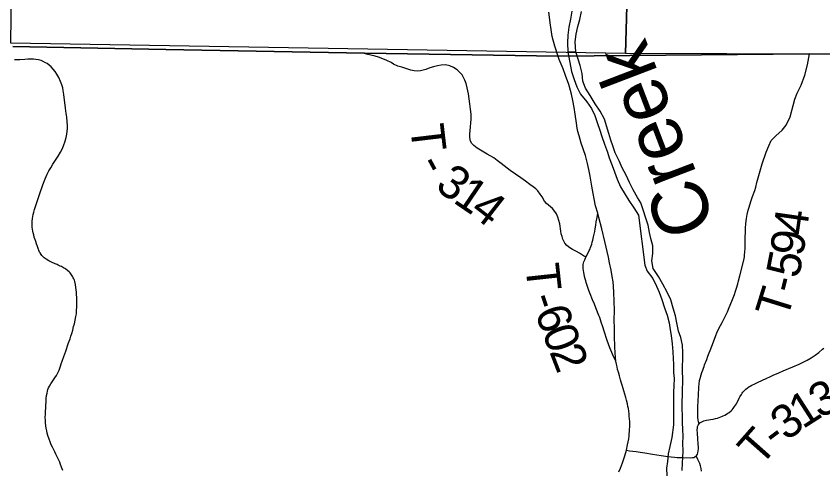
# Model space of a CAD drawing. Extents: x 0 to 34, y 0 to 22.
# Drawn here: x 4.406 to 5.767, y 16.7 to 17.465 of the extents above; entities that cross this region are included whole.
import ezdxf

# ---------------------------------------------------------------- set-up
doc = ezdxf.new("R2010")
doc.units = 0
for name, color, linetype in [('GM_X_Corporation', 7, 'Continuous'), ('GM_X_Major_River', 7, 'Continuous'), ('GM_X_Major_River_Text', 7, 'Continuous'), ('GM_X_State_Route', 7, 'Continuous'), ('GM_X_Township_Road', 7, 'Continuous'), ('GM_X_Township_Road_Text', 7, 'Continuous'), ('GM_X_Township_Text', 7, 'Continuous')]:
    doc.layers.add(name, color=color, linetype=linetype)

msp = doc.modelspace()

# ---------------------------------------------------------------- linework, layer by layer
at = {"layer": 'GM_X_Corporation'}
for points in [[(4.4097, 18.3961), (5.4623, 18.3997), (5.4343, 17.4017), (4.3969, 17.419)], [(6.4692, 18.391), (6.4651, 17.8343), (6.4606, 17.3985), (5.4343, 17.4017), (5.4623, 18.3997)]]:
    msp.add_lwpolyline(points, close=True, dxfattribs=at)
msp.add_lwpolyline([(8.9, 14.1), (8.9, 16.8499), (8.7964, 16.8516), (8.7214, 16.8529), (7.8171, 16.8691), (6.5825, 16.8858), (6.4571, 16.891), (6.4525, 17.3965), (6.1753, 17.3961), (5.7441, 17.4015), (5.3204, 17.3974), (4.9935, 17.4026), (4.6584, 17.4085), (4.4004, 17.4134)], dxfattribs=at)
at = {"layer": 'GM_X_Major_River'}
msp.add_line((5.3369, 17.4047), (5.3502, 17.4046), dxfattribs=at)
for points in [[(5.3438, 17.4732), (5.3411, 17.4598), (5.3383, 17.4461), (5.3367, 17.4328), (5.3362, 17.4199), (5.3369, 17.4047)], [(5.3502, 17.4046), (5.3494, 17.4213), (5.3507, 17.4342), (5.3534, 17.4472), (5.357, 17.4594), (5.3598, 17.4727)], [(5.3369, 17.4047), (5.3432, 17.3717), (5.3476, 17.3581), (5.3519, 17.3457), (5.3582, 17.3332), (5.3686, 17.3205), (5.3767, 17.3092), (5.3822, 17.2971), (5.3865, 17.2854), (5.3905, 17.2726), (5.394, 17.262), (5.3987, 17.2492), (5.4038, 17.2356), (5.4066, 17.2258), (5.4114, 17.213), (5.4153, 17.2024), (5.42, 17.19), (5.4255, 17.1771), (5.4336, 17.164), (5.4395, 17.1538), (5.4483, 17.1418), (5.4561, 17.129), (5.4669, 17.0447)], [(5.46, 17.15), (5.4542, 17.1593), (5.4468, 17.1717), (5.4409, 17.1845), (5.4351, 17.1966), (5.4285, 17.209), (5.4234, 17.2211), (5.4164, 17.2343), (5.4128, 17.246), (5.4093, 17.2558), (5.4061, 17.2667), (5.3989, 17.2909), (5.3912, 17.3045), (5.383, 17.3169), (5.3745, 17.3312), (5.3664, 17.3436), (5.362, 17.3553), (5.3607, 17.3682), (5.3575, 17.3814), (5.3502, 17.4046)], [(5.5297, 16.6987), (5.53, 16.7112), (5.531, 16.7215), (5.5313, 16.731), (5.5308, 16.7454), (5.5311, 16.7556), (5.5306, 16.7689), (5.5301, 16.7788), (5.5298, 16.8156), (5.5301, 16.8251), (5.5303, 16.8357), (5.5306, 16.8471), (5.5304, 16.8726), (5.531, 16.8881), (5.5309, 16.898), (5.5304, 16.9102), (5.5273, 16.923), (5.5237, 16.9336), (5.5206, 16.9476), (5.5182, 16.9594), (5.5146, 16.9726), (5.5107, 16.9867), (5.5045, 16.9995), (5.4968, 17.0131), (5.4899, 17.0259), (5.481, 17.0391), (5.4786, 17.052), (5.48, 17.0646), (5.4799, 17.0778), (5.4767, 17.09), (5.4744, 17.1002), (5.4724, 17.1123), (5.46, 17.15)], [(5.4669, 17.0447), (5.4708, 17.0349), (5.48, 17.0224), (5.4866, 17.0096), (5.4909, 16.9994), (5.4955, 16.9869), (5.4998, 16.9733), (5.5041, 16.9608), (5.508, 16.9479), (5.5093, 16.9358), (5.5109, 16.9263), (5.5126, 16.9123), (5.5138, 16.899), (5.5147, 16.8876), (5.5152, 16.8774), (5.5153, 16.8641), (5.5161, 16.8538), (5.5155, 16.8413), (5.5152, 16.831), (5.5149, 16.8212), (5.515, 16.8109), (5.5148, 16.7972), (5.515, 16.7756), (5.5121, 16.7543), (5.5089, 16.7391), (5.5063, 16.7269), (5.5049, 16.714), (5.5035, 16.7026), (5.5036, 16.6897)]]:
    msp.add_lwpolyline(points, dxfattribs=at)
at = {"layer": 'GM_X_State_Route'}
for points in [[(5.308, 17.4463), (5.3075, 17.4494), (5.3046, 17.4715)], [(5.3206, 17.3968), (5.3147, 17.4143), (5.3105, 17.4303), (5.308, 17.4463)], [(5.4228, 16.6966), (5.4254, 16.7027), (5.4288, 16.712), (5.4328, 16.7237), (5.4355, 16.7329), (5.4377, 16.7423), (5.4395, 16.752), (5.4401, 16.7565), (5.4405, 16.7605), (5.4409, 16.7645), (5.441, 16.7679), (5.4412, 16.7725), (5.4412, 16.7772), (5.4411, 16.7814), (5.4409, 16.7858), (5.4405, 16.7903), (5.4401, 16.7944), (5.4395, 16.799), (5.4389, 16.8031), (5.4382, 16.8068), (5.4372, 16.8114), (5.4359, 16.8171), (5.4347, 16.8216), (5.4331, 16.8276), (5.4315, 16.8331), (5.4303, 16.8371), (5.4287, 16.8424), (5.427, 16.8477), (5.4257, 16.8518), (5.4238, 16.8583), (5.4221, 16.8644), (5.4208, 16.8689), (5.4198, 16.8734), (5.4189, 16.8783), (5.418, 16.8831), (5.4172, 16.89), (5.4166, 16.8968), (5.416, 16.908), (5.4158, 16.9123), (5.4156, 16.9204), (5.4155, 16.9272), (5.4153, 16.9365), (5.4153, 16.9427), (5.4152, 16.9482), (5.4151, 16.9526), (5.4153, 16.9687), (5.4151, 16.9843), (5.4146, 16.9991), (5.4138, 17.0096), (5.413, 17.017), (5.4118, 17.0256), (5.4098, 17.0365), (5.4073, 17.0487), (5.4053, 17.0584), (5.3993, 17.0851), (5.3942, 17.1062), (5.389, 17.1254), (5.3872, 17.1324), (5.3837, 17.1452), (5.3811, 17.1567), (5.3793, 17.1659), (5.3773, 17.1782), (5.3746, 17.1953), (5.3724, 17.2063), (5.37, 17.2165), (5.3663, 17.2296), (5.3593, 17.2509), (5.3557, 17.2628), (5.3539, 17.2701), (5.3526, 17.2762), (5.3513, 17.2842), (5.3494, 17.2996), (5.3477, 17.3106), (5.3454, 17.3228), (5.3431, 17.333), (5.3414, 17.3396), (5.3382, 17.3495), (5.3328, 17.3647), (5.3287, 17.3757), (5.3223, 17.3919), (5.3206, 17.3968)]]:
    msp.add_lwpolyline(points, dxfattribs=at)
at = {"layer": 'GM_X_Township_Road'}
for points in [[(5.3673, 17.0584), (5.3653, 17.0595), (5.363, 17.0608), (5.3562, 17.0651), (5.3512, 17.068), (5.3446, 17.0715), (5.3404, 17.0744), (5.3352, 17.0784), (5.3315, 17.0822), (5.3281, 17.0889), (5.3272, 17.0931), (5.3258, 17.0977), (5.3252, 17.1023), (5.323, 17.1145), (5.3217, 17.12), (5.3199, 17.1259), (5.3177, 17.1313), (5.3146, 17.1353), (5.3108, 17.1404), (5.3007, 17.149), (5.2975, 17.1531), (5.2934, 17.1602), (5.2902, 17.1647), (5.2862, 17.1701), (5.2828, 17.1736), (5.2785, 17.1772), (5.2727, 17.1812), (5.2651, 17.1864), (5.2572, 17.1923), (5.2482, 17.1985), (5.2396, 17.2048), (5.2244, 17.2165), (5.2174, 17.2213), (5.2119, 17.2259), (5.2008, 17.2321), (5.1922, 17.237), (5.1836, 17.2423), (5.1783, 17.2469), (5.175, 17.25), (5.1727, 17.2543), (5.1716, 17.2604), (5.1713, 17.2661), (5.1722, 17.2718), (5.1739, 17.291), (5.1739, 17.2994), (5.1728, 17.3077), (5.1714, 17.3168), (5.1692, 17.334), (5.1672, 17.3442), (5.1652, 17.3511), (5.1629, 17.3569), (5.1606, 17.3616), (5.1583, 17.3658), (5.1553, 17.3694), (5.1501, 17.3741), (5.1436, 17.3784), (5.1375, 17.3812), (5.1302, 17.3828), (5.1231, 17.3823), (5.1168, 17.3812), (5.11, 17.3794), (5.1038, 17.3774), (5.0974, 17.3748), (5.0883, 17.3726), (5.0832, 17.3721), (5.0778, 17.3724), (5.072, 17.3735), (5.0649, 17.3758), (5.0567, 17.3787), (5.0502, 17.3807), (5.0429, 17.384), (5.0385, 17.3864), (5.0314, 17.39), (5.0247, 17.393), (5.0173, 17.3956), (5.0115, 17.3973), (5.0046, 17.3991), (4.9993, 17.4003), (4.9937, 17.402)], [(5.5581, 16.7772), (5.5572, 16.7809), (5.5565, 16.784), (5.556, 16.7884), (5.556, 16.7933), (5.556, 16.797), (5.5561, 16.8008), (5.5563, 16.8057), (5.5567, 16.8169), (5.557, 16.8256), (5.5577, 16.8393), (5.5582, 16.8448), (5.559, 16.8504), (5.5598, 16.8538), (5.5618, 16.8603), (5.563, 16.8638), (5.5643, 16.8681), (5.5654, 16.8711), (5.5665, 16.8742), (5.5676, 16.8768), (5.5686, 16.8795), (5.5697, 16.8822), (5.5713, 16.8862), (5.5732, 16.8914), (5.5754, 16.8971), (5.577, 16.9011), (5.5824, 16.9156), (5.5866, 16.9263), (5.5884, 16.9307), (5.5912, 16.9368), (5.5945, 16.9434), (5.5969, 16.9484), (5.6, 16.9539), (5.6035, 16.9609), (5.6061, 16.9663), (5.6091, 16.9736), (5.6133, 16.984), (5.6155, 16.9898), (5.6177, 16.9956), (5.6196, 17.0009), (5.6212, 17.006), (5.6235, 17.0133), (5.6247, 17.0187), (5.6271, 17.0271), (5.6337, 17.0536), (5.6347, 17.0591), (5.6351, 17.0621), (5.6356, 17.0677), (5.6359, 17.0732), (5.636, 17.0782), (5.6361, 17.0794), (5.6361, 17.0818), (5.6361, 17.0831), (5.6361, 17.0861), (5.6362, 17.0928), (5.6363, 17.1001), (5.6366, 17.1075), (5.6372, 17.115), (5.6381, 17.1236), (5.6393, 17.1304), (5.641, 17.1376), (5.6425, 17.143), (5.6436, 17.1466), (5.6462, 17.1541), (5.6485, 17.1609), (5.652, 17.1711), (5.6537, 17.1764), (5.6558, 17.1841), (5.6645, 17.2159), (5.6714, 17.2356), (5.6761, 17.2459), (5.68, 17.2549), (5.6877, 17.2631), (5.6983, 17.2728), (5.7052, 17.2809), (5.7121, 17.2953), (5.7168, 17.3141), (5.7196, 17.325), (5.7236, 17.3347), (5.7302, 17.3482), (5.7365, 17.3653), (5.7412, 17.3825), (5.7443, 17.401)], [(4.4848, 16.6987), (4.4828, 16.7043), (4.481, 16.7089), (4.4795, 16.7128), (4.4774, 16.7174), (4.4753, 16.7219), (4.4731, 16.7263), (4.4712, 16.7302), (4.4689, 16.7346), (4.4673, 16.7379), (4.4652, 16.7423), (4.4633, 16.7469), (4.4615, 16.7518), (4.4595, 16.7578), (4.4585, 16.7617), (4.4576, 16.7657), (4.4567, 16.77), (4.4562, 16.7741), (4.4557, 16.7791), (4.4554, 16.7832), (4.4552, 16.7885), (4.4553, 16.793), (4.4555, 16.7982), (4.4559, 16.8046), (4.4561, 16.8092), (4.4564, 16.8142), (4.4569, 16.8201), (4.4575, 16.8252), (4.4581, 16.8293), (4.4588, 16.8328), (4.4595, 16.8355), (4.4608, 16.8382), (4.4622, 16.8408), (4.4648, 16.8451), (4.4667, 16.8482), (4.4692, 16.8517), (4.4715, 16.8553), (4.4739, 16.859), (4.4764, 16.8634), (4.4786, 16.868), (4.4798, 16.8711), (4.4808, 16.8745), (4.4822, 16.8786), (4.4836, 16.883), (4.4867, 16.8911), (4.4899, 16.8999), (4.4911, 16.9034), (4.4929, 16.9087), (4.4946, 16.9139), (4.497, 16.921), (4.4983, 16.9252), (4.4997, 16.9299), (4.5015, 16.9355), (4.503, 16.9413), (4.5044, 16.9461), (4.5058, 16.9522), (4.5069, 16.9586), (4.5076, 16.963), (4.508, 16.9684), (4.5083, 16.9746), (4.5083, 16.9802), (4.5083, 16.9864), (4.5077, 16.9994), (4.507, 17.0075), (4.5062, 17.0123), (4.5049, 17.0172), (4.5042, 17.0195), (4.5032, 17.0218), (4.5025, 17.0234), (4.5017, 17.0252), (4.5006, 17.027), (4.4994, 17.0289), (4.497, 17.0318), (4.4953, 17.0336), (4.4935, 17.0353), (4.4919, 17.0366), (4.4901, 17.038), (4.4881, 17.0394), (4.486, 17.0407), (4.4827, 17.0425), (4.4805, 17.0435), (4.4772, 17.0451), (4.4755, 17.0459), (4.4721, 17.0473), (4.4709, 17.0477), (4.467, 17.0494), (4.461, 17.0525), (4.4567, 17.055), (4.4532, 17.0576), (4.4505, 17.0602), (4.4493, 17.0614), (4.4481, 17.063), (4.4464, 17.0656), (4.4457, 17.0669), (4.4449, 17.0684), (4.4432, 17.073), (4.442, 17.0765), (4.4403, 17.0812), (4.4391, 17.0847), (4.4376, 17.0894), (4.4367, 17.0923), (4.4357, 17.0959), (4.4347, 17.0994), (4.4341, 17.1024), (4.4337, 17.1057), (4.4333, 17.1093), (4.4332, 17.1122), (4.4331, 17.1151), (4.4331, 17.1187), (4.4337, 17.1236), (4.4343, 17.1273), (4.435, 17.1303), (4.4361, 17.1346), (4.4372, 17.1387), (4.4402, 17.1489), (4.4452, 17.1642), (4.4511, 17.1806), (4.4551, 17.1904), (4.4586, 17.1983), (4.4614, 17.2038), (4.4644, 17.2093), (4.4681, 17.215), (4.4772, 17.229), (4.481, 17.2354), (4.4841, 17.2415), (4.4866, 17.2478), (4.4882, 17.2525), (4.4904, 17.2603), (4.4916, 17.2657), (4.4923, 17.2707), (4.4926, 17.275), (4.4925, 17.2799), (4.492, 17.2874), (4.4913, 17.2947), (4.4909, 17.2978), (4.4906, 17.3008), (4.4894, 17.3094), (4.4881, 17.3192), (4.4872, 17.3278), (4.4866, 17.3328), (4.4856, 17.3394), (4.4847, 17.3437), (4.4831, 17.3491), (4.4809, 17.3549), (4.478, 17.3611), (4.4746, 17.367), (4.4716, 17.3717), (4.4685, 17.3756), (4.4651, 17.3793), (4.4619, 17.3822), (4.4584, 17.3847), (4.4557, 17.3863), (4.4518, 17.3882), (4.448, 17.3898), (4.4438, 17.391), (4.4395, 17.3917), (4.4351, 17.3922), (4.4307, 17.3922), (4.4258, 17.3922), (4.4208, 17.3919), (4.4122, 17.3914), (4.4035, 17.3909)], [(5.3673, 17.0584), (5.3677, 17.0592), (5.373, 17.0697), (5.3742, 17.0723), (5.3752, 17.0748), (5.3763, 17.0776), (5.377, 17.0801), (5.3781, 17.0837), (5.379, 17.0872), (5.3803, 17.0929), (5.3813, 17.0974), (5.3821, 17.1017), (5.3829, 17.106), (5.3839, 17.1125), (5.3847, 17.1178), (5.386, 17.1255), (5.3872, 17.1324)], [(5.418, 16.8831), (5.4123, 16.8949), (5.411, 16.8976), (5.4078, 16.9057), (5.4034, 16.9179), (5.3981, 16.9337), (5.3958, 16.9408), (5.3931, 16.949), (5.3905, 16.9566), (5.3892, 16.96), (5.3841, 16.973), (5.3816, 16.9793), (5.3786, 16.9866), (5.3744, 16.9969), (5.3723, 17.002), (5.371, 17.0055), (5.3697, 17.0091), (5.3687, 17.0125), (5.3678, 17.0159), (5.367, 17.0188), (5.3661, 17.0218), (5.3649, 17.0259), (5.3641, 17.0296), (5.3635, 17.0325), (5.3631, 17.0359), (5.3628, 17.0395), (5.3627, 17.0416), (5.3628, 17.0441), (5.3629, 17.0459), (5.3633, 17.0483), (5.3639, 17.0507), (5.3652, 17.0542), (5.3668, 17.0575), (5.3673, 17.0584)], [(5.5581, 16.7772), (5.5596, 16.779), (5.5616, 16.7805), (5.5637, 16.7816), (5.5661, 16.7824), (5.5709, 16.7834), (5.5745, 16.7841), (5.5775, 16.7845), (5.5819, 16.7854), (5.586, 16.7862), (5.5895, 16.7873), (5.5919, 16.7881), (5.5948, 16.7891), (5.5976, 16.7903), (5.5988, 16.7908), (5.6015, 16.7921), (5.6047, 16.794), (5.6068, 16.7953), (5.6088, 16.7968), (5.6121, 16.7995), (5.6139, 16.8013), (5.6159, 16.8036), (5.6182, 16.8066), (5.6199, 16.8091), (5.6211, 16.8112), (5.6224, 16.8136), (5.626, 16.8207), (5.6271, 16.8229), (5.6296, 16.8272), (5.631, 16.8293), (5.6321, 16.8307), (5.6346, 16.8335), (5.6373, 16.8361), (5.6392, 16.8377), (5.6423, 16.8397), (5.6444, 16.8409), (5.6471, 16.8424), (5.6522, 16.8448), (5.6578, 16.8475), (5.6712, 16.8538), (5.6785, 16.8572), (5.683, 16.8593), (5.6926, 16.8636), (5.7001, 16.8668), (5.7161, 16.8735), (5.7269, 16.8782), (5.7303, 16.8797), (5.7337, 16.8813), (5.737, 16.8829), (5.7403, 16.8846), (5.7473, 16.8887), (5.754, 16.8931), (5.7604, 16.898), (5.7666, 16.9032), (5.7685, 16.9048)], [(5.5531, 16.7233), (5.5545, 16.7249), (5.5553, 16.7265), (5.5562, 16.7288), (5.5568, 16.7319), (5.5571, 16.7352), (5.5571, 16.738), (5.5568, 16.743), (5.5562, 16.7523), (5.5553, 16.7616), (5.5551, 16.7672), (5.5553, 16.7702), (5.5558, 16.7727), (5.5567, 16.775), (5.5581, 16.7772)], [(5.4355, 16.7329), (5.4409, 16.7322), (5.4519, 16.7308), (5.4587, 16.7297), (5.4666, 16.7284), (5.4795, 16.7264), (5.4942, 16.7242), (5.5052, 16.7225), (5.5169, 16.7211), (5.5213, 16.7208), (5.5237, 16.7207), (5.5293, 16.7206), (5.5442, 16.7202), (5.5473, 16.7205), (5.5491, 16.7209), (5.5509, 16.7216), (5.5531, 16.7233)], [(5.5621, 16.6979), (5.5616, 16.7022), (5.5607, 16.7065), (5.5594, 16.7106), (5.5573, 16.7152), (5.5562, 16.7174), (5.5531, 16.7233)]]:
    msp.add_lwpolyline(points, dxfattribs=at)
at = {"layer": 'GM_X_Township_Text'}
msp.add_lwpolyline([(4.4004, 17.4134), (4.6584, 17.4085), (4.9935, 17.4026), (5.3204, 17.3974), (5.7441, 17.4015), (6.1753, 17.3961), (6.4525, 17.3965), (6.4571, 16.891), (6.5825, 16.8858), (7.8171, 16.8691), (8.7214, 16.8529), (8.7964, 16.8516), (8.9, 16.8499)], dxfattribs=at)

# ---------------------------------------------------------------- texts
at = {"layer": 'GM_X_Major_River_Text'}
msp.add_text('Creek', height=0.09469, rotation=110.9056, dxfattribs=at).set_placement((5.5875, 17.1135))
at = {"layer": 'GM_X_Township_Road_Text'}
for s, rotation, p in [('T', 276.7827, (5.0705, 17.2796)), ('-', 298.3597, (5.0825, 17.2153)), ('3', 323.0882, (5.1109, 17.1746)), ('1', 325.7708, (5.1413, 17.1519)), ('4', 322.031, (5.1694, 17.1328)), ('4', 81.8922, (5.7388, 17.0934)), ('9', 81.2838, (5.7334, 17.0582)), ('5', 79.0728, (5.7264, 17.0214)), ('T', 276.1921, (5.265, 17.045)), ('-', 75.7988, (5.7199, 16.9954)), ('T', 72.7117, (5.7064, 16.9516)), ('-', 288.6001, (5.2725, 16.9897)), ('6', 290.0661, (5.2805, 16.9661)), ('0', 290.4708, (5.2926, 16.9328)), ('2', 291.1786, (5.3051, 16.8993)), ('3', 26.0856, (5.7611, 16.786)), ('1', 32.6855, (5.7331, 16.7679)), ('3', 36.8699, (5.706, 16.7475)), ('T', 48.5601, (5.6615, 16.7037)), ('-', 36.9698, (5.6874, 16.7335))]:
    msp.add_text(s, height=0.0568, rotation=rotation, dxfattribs=at).set_placement(p)

doc.saveas('drawing.dxf')
